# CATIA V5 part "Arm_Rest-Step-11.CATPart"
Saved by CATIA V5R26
Part number: Arm_Rest
Bounding box of the stored display mesh (mm): x 766.594 to 1406.039, y -781.99 to -669.51, z 394.789 to 524.009
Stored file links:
  D:\LinkedIn Learning\NURBS\CATIA\Class Parts\Arm_Rest-Step-12.CATPart
  D:\LinkedIn Learning\NURBS\Arm_Rest.CATPart
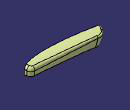
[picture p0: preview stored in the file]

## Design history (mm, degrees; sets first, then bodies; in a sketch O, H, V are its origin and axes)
AxisSystem1: origin (0, 0, 0), X (1, 0, 0), Y (0, 1, 0), Z (0, 0, 1)
StDynAnalysisRootNodeFeature1 "CATStDynAnalysisRootNodeName"
Set1 "REF DATA"
  CLDGeom1 "TOP"
  CLDGeom2 "FRONT"
  CLDGeom3 "AFT_BLEND"
  CLDGeom4 "END_AFT"
  CLDGeom5 "FORWARD_BLEND"
  CLDGeom6 "BOTTOM"
  CLDGeom7 "END_FORWARD"
  CLDGeom8 "UPPER_BLENDS"
  CLDGeom9 "LOWER_BLENDS"
  DatumSurface1 "DOOR_TRIM_SURFACE"
Set2 "FORM"
  Set3 "SLABS"
    DatumSurface2 to DatumSurface6
  Set4 "CURVES"
    St3DCurveFeature1 "CATSt3DCurveFeatureName": Order 6, CreationType 1, ClosureMode false, ConstructionPoints ({point type Coord, X 863.1168, Y 0, Z 551.1449}; {point type Coord, X 868.9503, Y 0, Z 330.43}), SymmetryMode false
    St3DCurveFeature2 "CATSt3DCurveFeatureName": Order 6, CreationType 1, ClosureMode false, ConstructionPoints ({point type Coord, X 1369.3867, Y 0, Z 551.9965}; {point type Coord, X 1358.4038, Y 0, Z 335.6826}), SymmetryMode false
    Intersect1: ToIntersect1 DatumSurface4, ToIntersect2 DatumSurface5
    Intersect2: ToIntersect1 DatumSurface6, ToIntersect2 DatumSurface4
    CurvePar1: Offset Intersect2, Support DatumSurface6, Offset2 0, Offset1 30
    CurvePar2: Offset Intersect1, Support DatumSurface5, Offset2 50, Offset1 20
    Project1: ToProject St3DCurveFeature1, Support DatumSurface4, Direction edge [YZ plane of AxisSystem1 | XY plane of AxisSystem1]
    Project2: ToProject St3DCurveFeature2, Support DatumSurface4, Direction edge [YZ plane of AxisSystem1 | XY plane of AxisSystem1]
    Project3: ToProject St3DCurveFeature2, Support StTopoTypeFeature3, Direction edge [YZ plane of AxisSystem1 | XY plane of AxisSystem1]
    Project4: ToProject St3DCurveFeature1, Support StTopoTypeFeature3, Direction edge [YZ plane of AxisSystem1 | XY plane of AxisSystem1]
    Intersect3: ToIntersect1 edge of StTopoTypeFeature1, ToIntersect2 CurvePar2
    Intersect4: ToIntersect1 edge of StTopoTypeFeature2, ToIntersect2 CurvePar1
    Project5: ToProject Intersect4, Support edge of StTopoTypeFeature2
    Project6: ToProject Intersect3, Support edge of StTopoTypeFeature1
    Line1: type PtPt, FirstPoint Intersect3, SecondPoint Project6, Support StTopoTypeFeature1
    Line2: type PtPt, FirstPoint Intersect4, SecondPoint Project5, Support StTopoTypeFeature2
    Curve1: Elements (Intersect4; vertex of Project3), Support Blend2
    Curve2: Elements (Project5; vertex of Project3), Support DatumSurface2
    Curve3: Elements (vertex of Project4; Intersect3), Support Blend1
    Curve4: Elements (vertex of Project4; Project6), Support DatumSurface2
  Set5 "BLENDS"
    Blend1: StartLimit {blendlimit Curve Project1, Support DatumSurface4, TensionValues 1.1}, EndLimit {blendlimit Curve CurvePar2, Support DatumSurface5, TensionValues 1}
    Blend2: StartLimit {blendlimit Curve CurvePar1, Support DatumSurface6, TensionValues 0.9}, EndLimit {blendlimit Curve Project2, Support DatumSurface4, TensionValues 0.8}
    StTopoTypeFeature1 "CATStTopoTypeFeatureName": Children 15
    StTopoTypeFeature2 "CATStTopoTypeFeatureName": Children 35
    StTopoTypeFeature3 "CATStTopoTypeFeatureName": nls://CATStFeaturesStartUpsNLS/TopoVarRadiCke 35, nls://CATStFeaturesStartUpsNLS/TopoVarRadiCke 15
    Loft1: Sections (Line2; Project3), StartSectionTangent StTopoTypeFeature2, EndSectionTangent StTopoTypeFeature3, Guides ({loftguide GuideCurve Curve1, GuideTangent Blend2}; {loftguide GuideCurve Curve2, GuideTangent DatumSurface2})
    Loft2: Sections (Project4; Line1), StartSectionTangent StTopoTypeFeature3, EndSectionTangent StTopoTypeFeature1, Guides ({loftguide GuideCurve Curve3, GuideTangent Blend1}; {loftguide GuideCurve Curve4, GuideTangent DatumSurface2})
  Set6 "SPLITS"
    Split1: ToCut DatumSurface4, Cutting (Project1; edge of StTopoTypeFeature3; Project2)
    Split2: ToCut Blend2, Cutting Curve1
    Split3: ToCut DatumSurface6, Cutting (CurvePar1; edge of StTopoTypeFeature2)
    Split4: ToCut Blend1, Cutting Curve3
    Split5: ToCut DatumSurface5, Cutting (CurvePar2; edge of StTopoTypeFeature1)
    Split6: ToCut StTopoTypeFeature1, Cutting Line1
    Split7: ToCut StTopoTypeFeature3, Cutting (Project4; Project3)
    Split8: ToCut StTopoTypeFeature2, Cutting Line2
    Split9: ToCut DatumSurface2, Cutting (edge of StTopoTypeFeature3; edge of StTopoTypeFeature2; Curve2; edge of StTopoTypeFeature1; Curve4)
  Join1: Elements (Split9; Loft1; Loft2; Split6; Split7; Split8; Split2; Split4; Split5; Split1; Split3)
  StTopoTypeFeature4 "CATStTopoTypeFeatureName": Children 13
  Split10: ToCut StTopoTypeFeature4, Cutting DatumSurface1
Body1 (main body)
